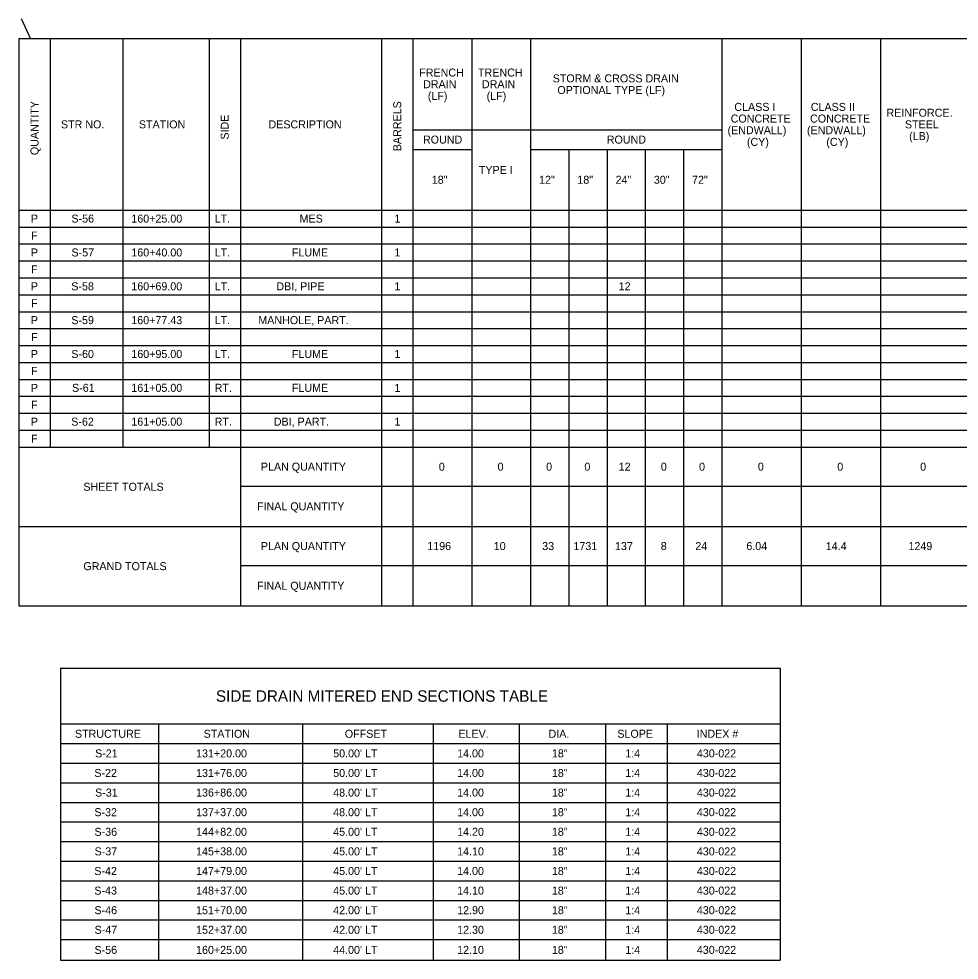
# Model space of a CAD drawing. Extents: x 0 to 765, y -1227 to 479.
# Drawn here: x 0.3 to 360, y -1081.9 to -721.8 of the extents above; entities that cross this region are included whole.
import ezdxf

# ---------------------------------------------------------------- set-up
doc = ezdxf.new("R2010")
doc.units = 0
for name, color, linetype in [('Miscellaneous0', 7, 'Continuous'), ('PlotBorder_dp', 7, 'Continuous'), ('SheetLines_dp', 7, 'Continuous'), ('TextMinor', 7, 'Continuous'), ('TextShtNo', 7, 'Continuous')]:
    doc.layers.add(name, color=color, linetype=linetype)

msp = doc.modelspace()

# ---------------------------------------------------------------- linework, layer by layer
at = {"layer": 'PlotBorder_dp'}
for p, q in [((12.29, -729.34), (12.29, -885.61)), ((12.29, -729.34), (12.29, -885.61)), ((40.04, -729.34), (40.04, -885.61)), ((40.04, -729.34), (40.04, -885.61)), ((73.04, -729.34), (73.04, -885.61)), ((85.04, -729.34), (85.04, -946.36)), ((139.04, -729.34), (139.04, -946.36)), ((151.04, -729.34), (151.04, -946.36)), ((151.04, -729.34), (151.04, -946.36)), ((173.54, -729.34), (173.54, -946.36)), ((173.54, -729.34), (173.54, -946.36)), ((196.04, -729.34), (196.04, -946.36)), ((196.04, -729.34), (196.04, -946.36)), ((269.16, -729.34), (269.16, -946.36)), ((269.16, -729.34), (269.16, -946.36)), ((299.54, -729.34), (299.54, -946.36)), ((299.54, -729.34), (299.54, -946.36)), ((329.91, -729.34), (329.91, -946.36)), ((329.91, -729.34), (329.91, -946.36)), ((151.04, -764.21), (269.16, -764.21)), ((151.04, -771.71), (173.54, -771.71)), ((151.04, -771.71), (173.54, -771.71)), ((196.04, -771.71), (269.16, -771.71)), ((196.04, -771.71), (269.16, -771.71)), ((210.66, -771.71), (210.66, -946.36)), ((210.66, -771.71), (210.66, -946.36)), ((225.29, -771.71), (225.29, -946.36)), ((225.29, -771.71), (225.29, -946.36)), ((239.91, -771.71), (239.91, -946.36)), ((239.91, -771.71), (239.91, -946.36)), ((254.54, -771.71), (254.54, -900.61)), ((254.54, -771.71), (254.54, -946.36)), ((73.04, -794.96), (73.04, -885.61)), ((85.04, -794.96), (85.04, -946.36)), ((139.04, -794.96), (139.04, -946.36)), ((0.29, -885.61), (764.54, -885.61)), ((85.04, -900.61), (764.54, -900.61)), ((85.04, -900.61), (764.54, -900.61)), ((0.29, -915.99), (764.54, -915.99)), ((254.54, -915.99), (254.54, -930.99)), ((85.04, -930.99), (764.54, -930.99)), ((85.04, -930.99), (764.54, -930.99)), ((16.24, -991.56), (291.49, -991.56)), ((16.24, -991.56), (291.49, -991.56)), ((53.74, -991.56), (53.74, -1081.93)), ((53.74, -991.56), (53.74, -1081.93)), ((108.86, -991.56), (108.86, -1081.93)), ((108.86, -991.56), (108.86, -1081.93)), ((158.74, -991.56), (158.74, -1081.93)), ((158.74, -991.56), (158.74, -1081.93)), ((191.74, -991.56), (191.74, -1081.93)), ((191.74, -991.56), (191.74, -1081.93)), ((224.74, -991.56), (224.74, -1081.93)), ((224.74, -991.56), (224.74, -1081.93)), ((248.36, -991.56), (248.36, -1081.93)), ((248.36, -991.56), (248.36, -1081.93)), ((16.24, -999.06), (291.49, -999.06)), ((16.24, -999.06), (291.49, -999.06)), ((16.24, -1006.56), (291.49, -1006.56)), ((16.24, -1006.56), (291.49, -1006.56)), ((16.24, -1014.06), (291.49, -1014.06)), ((16.24, -1014.06), (291.49, -1014.06)), ((16.24, -1021.56), (291.49, -1021.56)), ((16.24, -1021.56), (291.49, -1021.56)), ((16.24, -1029.06), (53.74, -1029.06)), ((16.24, -1029.06), (291.49, -1029.06)), ((108.86, -1029.06), (291.49, -1029.06)), ((16.24, -1036.56), (291.49, -1036.56)), ((16.24, -1036.56), (291.49, -1036.56)), ((16.24, -1044.06), (291.49, -1044.06)), ((16.24, -1044.06), (291.49, -1044.06)), ((16.24, -1051.56), (291.49, -1051.56)), ((16.24, -1051.56), (291.49, -1051.56)), ((16.24, -1059.06), (291.49, -1059.06)), ((16.24, -1059.06), (291.49, -1059.06)), ((16.24, -1066.56), (291.49, -1066.56)), ((16.24, -1066.56), (291.49, -1066.56)), ((16.24, -1074.06), (291.49, -1074.06)), ((16.24, -1074.06), (291.49, -1074.06))]:
    msp.add_line(p, q, dxfattribs=at)
at = {"layer": 'SheetLines_dp'}
for p, q in [((0.29, -729.34), (764.54, -729.34)), ((0.29, -729.34), (0.29, -946.36)), ((0.29, -794.96), (764.54, -794.96)), ((0.29, -794.96), (12.29, -794.96)), ((40.04, -794.96), (151.04, -794.96)), ((173.54, -794.96), (406.79, -794.96)), ((0.29, -915.99), (764.54, -915.99)), ((0.29, -946.36), (764.54, -946.36)), ((16.24, -970.18), (291.49, -970.18)), ((16.24, -970.18), (16.24, -1081.93)), ((291.49, -970.18), (291.49, -1081.93)), ((16.24, -1081.93), (291.49, -1081.93))]:
    msp.add_line(p, q, dxfattribs=at)
at = {"layer": 'TextMinor'}
for p, q in [((12.29, -794.96), (40.04, -794.96)), ((151.04, -794.96), (173.54, -794.96)), ((0.29, -801.44), (764.54, -801.44)), ((0.29, -801.44), (764.54, -801.44)), ((0.29, -807.91), (764.54, -807.91)), ((0.29, -807.91), (764.54, -807.91)), ((0.29, -814.39), (764.54, -814.39)), ((0.29, -814.39), (764.54, -814.39)), ((0.29, -820.86), (151.04, -820.86)), ((0.29, -820.86), (764.54, -820.86)), ((173.54, -820.86), (764.54, -820.86)), ((0.29, -827.34), (196.04, -827.34)), ((0.29, -827.34), (764.54, -827.34)), ((210.66, -827.34), (406.79, -827.34)), ((0.29, -833.81), (764.54, -833.81)), ((0.29, -833.81), (764.54, -833.81)), ((0.29, -840.29), (764.54, -840.29)), ((0.29, -840.29), (764.54, -840.29)), ((0.29, -846.76), (764.54, -846.76)), ((0.29, -846.76), (764.54, -846.76)), ((0.29, -853.24), (764.54, -853.24)), ((0.29, -853.24), (764.54, -853.24)), ((0.29, -859.71), (764.54, -859.71)), ((0.29, -859.71), (764.54, -859.71)), ((0.29, -866.19), (764.54, -866.19)), ((0.29, -866.19), (764.54, -866.19)), ((0.29, -872.66), (764.54, -872.66)), ((0.29, -872.66), (764.54, -872.66)), ((0.29, -879.14), (764.54, -879.14)), ((0.29, -879.14), (764.54, -879.14)), ((0.29, -885.61), (764.54, -885.61)), ((53.74, -1029.06), (108.86, -1029.06))]:
    msp.add_line(p, q, dxfattribs=at)
at = {"layer": 'TextShtNo'}
msp.add_line((4.8, -729.34), (1.37, -721.76), dxfattribs=at)

# ---------------------------------------------------------------- texts
at = {"layer": 'Miscellaneous0'}
for s, height, p in [('FRENCH', 3.062, (153.45, -743.85)), ('TRENCH', 3.062, (175.95, -743.85)), ('DRAIN', 3.062, (154.94, -748.31)), ('DRAIN', 3.062, (177.44, -748.31)), ('STORM & CROSS DRAIN', 3.0625, (204.5, -746.08)), ('OPTIONAL TYPE (LF)', 3.0625, (206.3, -750.54)), ('(LF)', 3.062, (156.74, -752.77)), ('(LF)', 3.062, (179.24, -752.77)), (' CLASS I', 3.062, (272.87, -756.99)), ('CLASS II', 3.062, (303.25, -756.99)), ('REINFORCE.', 3.062, (332.2, -759.22)), ('CONCRETE', 3.062, (272.59, -761.45)), ('CONCRETE', 3.062, (302.97, -761.45)), ('STR NO.', 3.062, (16.4, -763.68)), ('STATION', 3.062, (46.22, -763.68)), ('DESCRIPTION', 3.0625, (95.79, -763.68)), ('(ENDWALL)', 3.062, (271.39, -765.91)), ('(ENDWALL)', 3.062, (301.77, -765.91)), ('STEEL', 3.062, (339.25, -763.68)), ('ROUND', 3.062, (154.89, -769.5)), ('ROUND', 3.062, (225.2, -769.5)), ('(CY)', 3.062, (278.8, -770.38)), ('(CY)', 3.062, (309.18, -770.38)), ('(LB)', 3.062, (340.86, -768.15)), ('TYPE I', 3.062, (176.27, -781.12)), ('18"', 3.062, (158.25, -784.87)), ('12"', 3.062, (199.31, -784.87)), ('18"', 3.062, (213.94, -784.87)), ('24"', 3.062, (228.56, -784.87)), ('30"', 3.062, (243.19, -784.87)), ('72"', 3.062, (257.81, -784.87)), ('P', 3.06, (4.9, -799.73)), ('S-56', 3.062, (20.41, -799.73)), ('160+25.00', 3.062, (43.33, -799.73)), ('LT.', 3.062, (75.2, -799.73)), ('MES', 3.062, (107.7, -799.73)), ('1', 3.06, (143.96, -799.73)), ('F', 3.06, (4.95, -806.21)), ('P', 3.06, (4.9, -812.68)), ('S-57', 3.062, (20.43, -812.68)), ('160+40.00', 3.062, (43.33, -812.68)), ('LT.', 3.062, (75.2, -812.68)), ('FLUME', 3.062, (104.73, -812.68)), ('1', 3.06, (143.96, -812.68)), ('F', 3.06, (4.95, -819.16)), ('P', 3.06, (4.9, -825.63)), ('S-58', 3.062, (20.35, -825.63)), ('160+69.00', 3.062, (43.33, -825.63)), ('LT.', 3.062, (75.2, -825.63)), ('DBI, PIPE', 3.062, (98.8, -825.63)), ('1', 3.06, (143.96, -825.63)), ('12', 3.062, (229.75, -825.63)), ('F', 3.06, (4.95, -832.11)), ('P', 3.06, (4.9, -838.58)), ('S-59', 3.062, (20.36, -838.58)), ('160+77.43', 3.062, (43.31, -838.58)), ('LT.', 3.062, (75.2, -838.58)), ('MANHOLE, PART.', 3.0625, (91.9, -838.58)), ('F', 3.06, (4.95, -845.06)), ('P', 3.06, (4.9, -851.53)), ('S-60', 3.062, (20.37, -851.53)), ('160+95.00', 3.062, (43.33, -851.53)), ('LT.', 3.062, (75.2, -851.53)), ('FLUME', 3.062, (104.73, -851.53)), ('1', 3.06, (143.96, -851.53)), ('F', 3.06, (4.95, -858.01)), ('P', 3.06, (4.9, -864.48)), ('S-61', 3.062, (20.64, -864.48)), ('161+05.00', 3.062, (43.33, -864.48)), ('RT.', 3.062, (75.2, -864.48)), ('FLUME', 3.062, (104.73, -864.48)), ('1', 3.06, (143.96, -864.48)), ('F', 3.06, (4.95, -870.96)), ('P', 3.06, (4.9, -877.43)), ('S-62', 3.062, (20.34, -877.43)), ('161+05.00', 3.062, (43.33, -877.43)), ('RT.', 3.062, (75.2, -877.43)), ('DBI, PART.', 3.062, (97.83, -877.43)), ('1', 3.06, (143.96, -877.43)), ('F', 3.06, (4.95, -883.91)), ('PLAN QUANTITY', 3.0625, (92.87, -894.65)), ('0', 3.06, (160.94, -894.65)), ('0', 3.06, (183.44, -894.65)), ('0', 3.06, (202, -894.65)), ('0', 3.06, (216.63, -894.65)), ('12', 3.062, (229.75, -894.65)), ('0', 3.06, (245.88, -894.65)), ('0', 3.06, (260.5, -894.65)), ('0', 3.06, (283, -894.65)), ('0', 3.06, (313.38, -894.65)), ('0', 3.06, (345.07, -894.65)), ('SHEET TOTALS', 3.0625, (24.98, -902.33)), ('FINAL QUANTITY', 3.0625, (91.39, -909.83)), ('PLAN QUANTITY', 3.0625, (92.87, -925.02)), ('1196', 3.062, (156.53, -925.02)), ('10', 3.062, (181.96, -925.02)), ('33', 3.062, (200.49, -925.02)), ('1731', 3.062, (212.45, -925.02)), ('137', 3.062, (228.35, -925.02)), ('8', 3.06, (245.86, -925.02)), ('24', 3.062, (259.06, -925.02)), ('6.04', 3.062, (278.59, -925.02)), ('14.4', 3.062, (308.97, -925.02)), ('1249', 3.062, (340.61, -925.02)), ('GRAND TOTALS', 3.0625, (24.98, -932.71)), ('FINAL QUANTITY', 3.0625, (91.39, -940.21)), ('SIDE DRAIN MITERED END SECTIONS TABLE', 4.375, (75.66, -983.06)), ('STRUCTURE', 3.062, (21.75, -996.84)), ('STATION', 3.062, (70.98, -996.84)), ('OFFSET', 3.062, (124.99, -996.84)), ('ELEV.', 3.062, (168.44, -996.84)), ('DIA.', 3.062, (202.92, -996.84)), ('SLOPE', 3.062, (229.24, -996.84)), ('INDEX #', 3.062, (259.6, -996.84)), ('S-21', 3.062, (29.46, -1004.34)), ('131+20.00', 3.062, (68.09, -1004.34)), ("50.00' LT", 3.062, (120.54, -1004.34)), ('14.00', 3.062, (167.96, -1004.34)), ('18"', 3.062, (204.2, -1004.34)), ('430-022', 3.062, (259.66, -1004.34)), ('1:4', 3.062, (232.27, -1004.34)), ('S-22', 3.062, (29.17, -1011.84)), ('131+76.00', 3.062, (68.09, -1011.84)), ("50.00' LT", 3.062, (120.54, -1011.84)), ('14.00', 3.062, (167.96, -1011.84)), ('18"', 3.062, (204.2, -1011.84)), ('1:4', 3.062, (232.27, -1011.84)), ('430-022', 3.062, (259.66, -1011.84)), ('S-31', 3.062, (29.46, -1019.34)), ('136+86.00', 3.062, (68.09, -1019.34)), ("48.00' LT", 3.062, (120.54, -1019.34)), ('14.00', 3.062, (167.96, -1019.34)), ('18"', 3.062, (204.2, -1019.34)), ('1:4', 3.062, (232.27, -1019.34)), ('430-022', 3.062, (259.66, -1019.34)), ('S-32', 3.062, (29.17, -1026.84)), ('137+37.00', 3.062, (68.09, -1026.84)), ("48.00' LT", 3.062, (120.54, -1026.84)), ('14.00', 3.062, (167.96, -1026.84)), ('18"', 3.062, (204.2, -1026.84)), ('1:4', 3.062, (232.27, -1026.84)), ('430-022', 3.062, (259.66, -1026.84)), ('S-36', 3.062, (29.23, -1034.34)), ('144+82.00', 3.062, (68.09, -1034.34)), ("45.00' LT", 3.062, (120.54, -1034.34)), ('14.20', 3.062, (167.96, -1034.34)), ('18"', 3.062, (204.2, -1034.34)), ('1:4', 3.062, (232.27, -1034.34)), ('430-022', 3.062, (259.66, -1034.34)), ('S-37', 3.062, (29.26, -1041.84)), ('145+38.00', 3.062, (68.09, -1041.84)), ("45.00' LT", 3.062, (120.54, -1041.84)), ('14.10', 3.062, (167.96, -1041.84)), ('18"', 3.062, (204.2, -1041.84)), ('1:4', 3.062, (232.27, -1041.84)), ('430-022', 3.062, (259.66, -1041.84)), ('S-42', 3.062, (29.17, -1049.34)), ('147+79.00', 3.062, (68.09, -1049.34)), ("45.00' LT", 3.062, (120.54, -1049.34)), ('14.00', 3.062, (167.96, -1049.34)), ('18"', 3.062, (204.2, -1049.34)), ('1:4', 3.062, (232.27, -1049.34)), ('430-022', 3.062, (259.66, -1049.34)), ('S-43', 3.062, (29.17, -1056.84)), ('148+37.00', 3.062, (68.09, -1056.84)), ("45.00' LT", 3.062, (120.54, -1056.84)), ('14.10', 3.062, (167.96, -1056.84)), ('18"', 3.062, (204.2, -1056.84)), ('1:4', 3.062, (232.27, -1056.84)), ('430-022', 3.062, (259.66, -1056.84)), ('S-46', 3.062, (29.23, -1064.34)), ('151+70.00', 3.062, (68.09, -1064.34)), ("42.00' LT", 3.062, (120.54, -1064.34)), ('12.90', 3.062, (167.96, -1064.34)), ('18"', 3.062, (204.2, -1064.34)), ('1:4', 3.062, (232.27, -1064.34)), ('430-022', 3.062, (259.66, -1064.34)), ('S-47', 3.062, (29.26, -1071.84)), ('152+37.00', 3.062, (68.09, -1071.84)), ("42.00' LT", 3.062, (120.54, -1071.84)), ('12.30', 3.062, (167.96, -1071.84)), ('18"', 3.062, (204.2, -1071.84)), ('1:4', 3.062, (232.27, -1071.84)), ('430-022', 3.062, (259.66, -1071.84)), ('S-56', 3.062, (29.23, -1079.53)), ('160+25.00', 3.062, (68.09, -1079.53)), ("44.00' LT", 3.062, (120.54, -1079.53)), ('12.10', 3.062, (167.96, -1079.53)), ('18"', 3.062, (204.2, -1079.53)), ('1:4', 3.062, (232.27, -1079.53)), ('430-022', 3.062, (259.66, -1079.53))]:
    msp.add_text(s, height=height, dxfattribs=at).set_placement(p)
for s, p in [('QUANTITY', (7.82, -773.91)), ('BARRELS', (146.57, -772.42)), ('SIDE', (80.57, -767.98))]:
    msp.add_text(s, height=3.062, rotation=90, dxfattribs=at).set_placement(p)

doc.saveas('drawing.dxf')
